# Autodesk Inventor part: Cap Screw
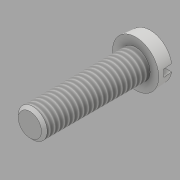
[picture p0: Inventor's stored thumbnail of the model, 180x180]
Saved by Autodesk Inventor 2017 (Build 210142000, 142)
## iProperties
Created: 2016-05
Part Number: Cap Screw
Material: Generic
Document SubType Name: Modeling
Designer: CADCIM
Density: 1 g/cm^3
Appearance: Default
Author: CADCIM
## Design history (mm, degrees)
sketch "Sketch2"
  geometry: C1 r 4.8 at (0, 0); 1 further point
  constraints: 1 centre point, 1 coincident
  dimensions: "d0" = 9.6 diameter of C1
extrude "Extrusion1" new body sketch "Sketch2" distance "d1" = 3; taper "d2" = -5 deg
sketch "Sketch3"
  geometry: C1 r 3 at (0, 0); 1 further point
  constraints: 1 centre point, 1 coincident
  dimensions: "d3" = 6 diameter of C1
extrude "Extrusion2" join sketch "Sketch3" distance "d4" = 22; taper "d5" = 0 deg
sketch "Sketch4"
  geometry: L1 (-13.358, -0.75)-(13.048, -0.75); L2 (13.048, -0.75)-(13.048, 0.75); L3 (13.048, 0.75)-(-13.358, 0.75); L4 (-13.358, 0.75)-(-13.358, -0.75); L5 (0, 0)-(-15.613, 0)
  constraints: 10 end point, 3 parallel, 1 horizontal, 1 perpendicular, 1 other
  dimensions: "d6" = 1.5 distance of L3.end L1.start
extrude "Extrusion3" cut sketch "Sketch4" distance "d7" = 1.8; taper "d8" = 0 deg
thread "Thread1" dims "d9" = 10, "d10" = 0
chamfer "Chamfer1" distance "d11" = 0.6; stored, may be unused: second distance "d12" = 2, angle "d13" = 45 deg
body "Solid1"
